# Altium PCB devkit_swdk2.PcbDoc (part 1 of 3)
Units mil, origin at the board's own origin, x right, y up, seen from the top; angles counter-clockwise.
Board outline 2700 x 2100 mil, 4 copper layers (Component Side, Internal Plane 1, Internal Layer 2, Bottom Layer), stack 57.8 mil thick; 223 components, 143 nets, 656 pads, 485 vias.
Unrouted connection lines stored in the file: 72.
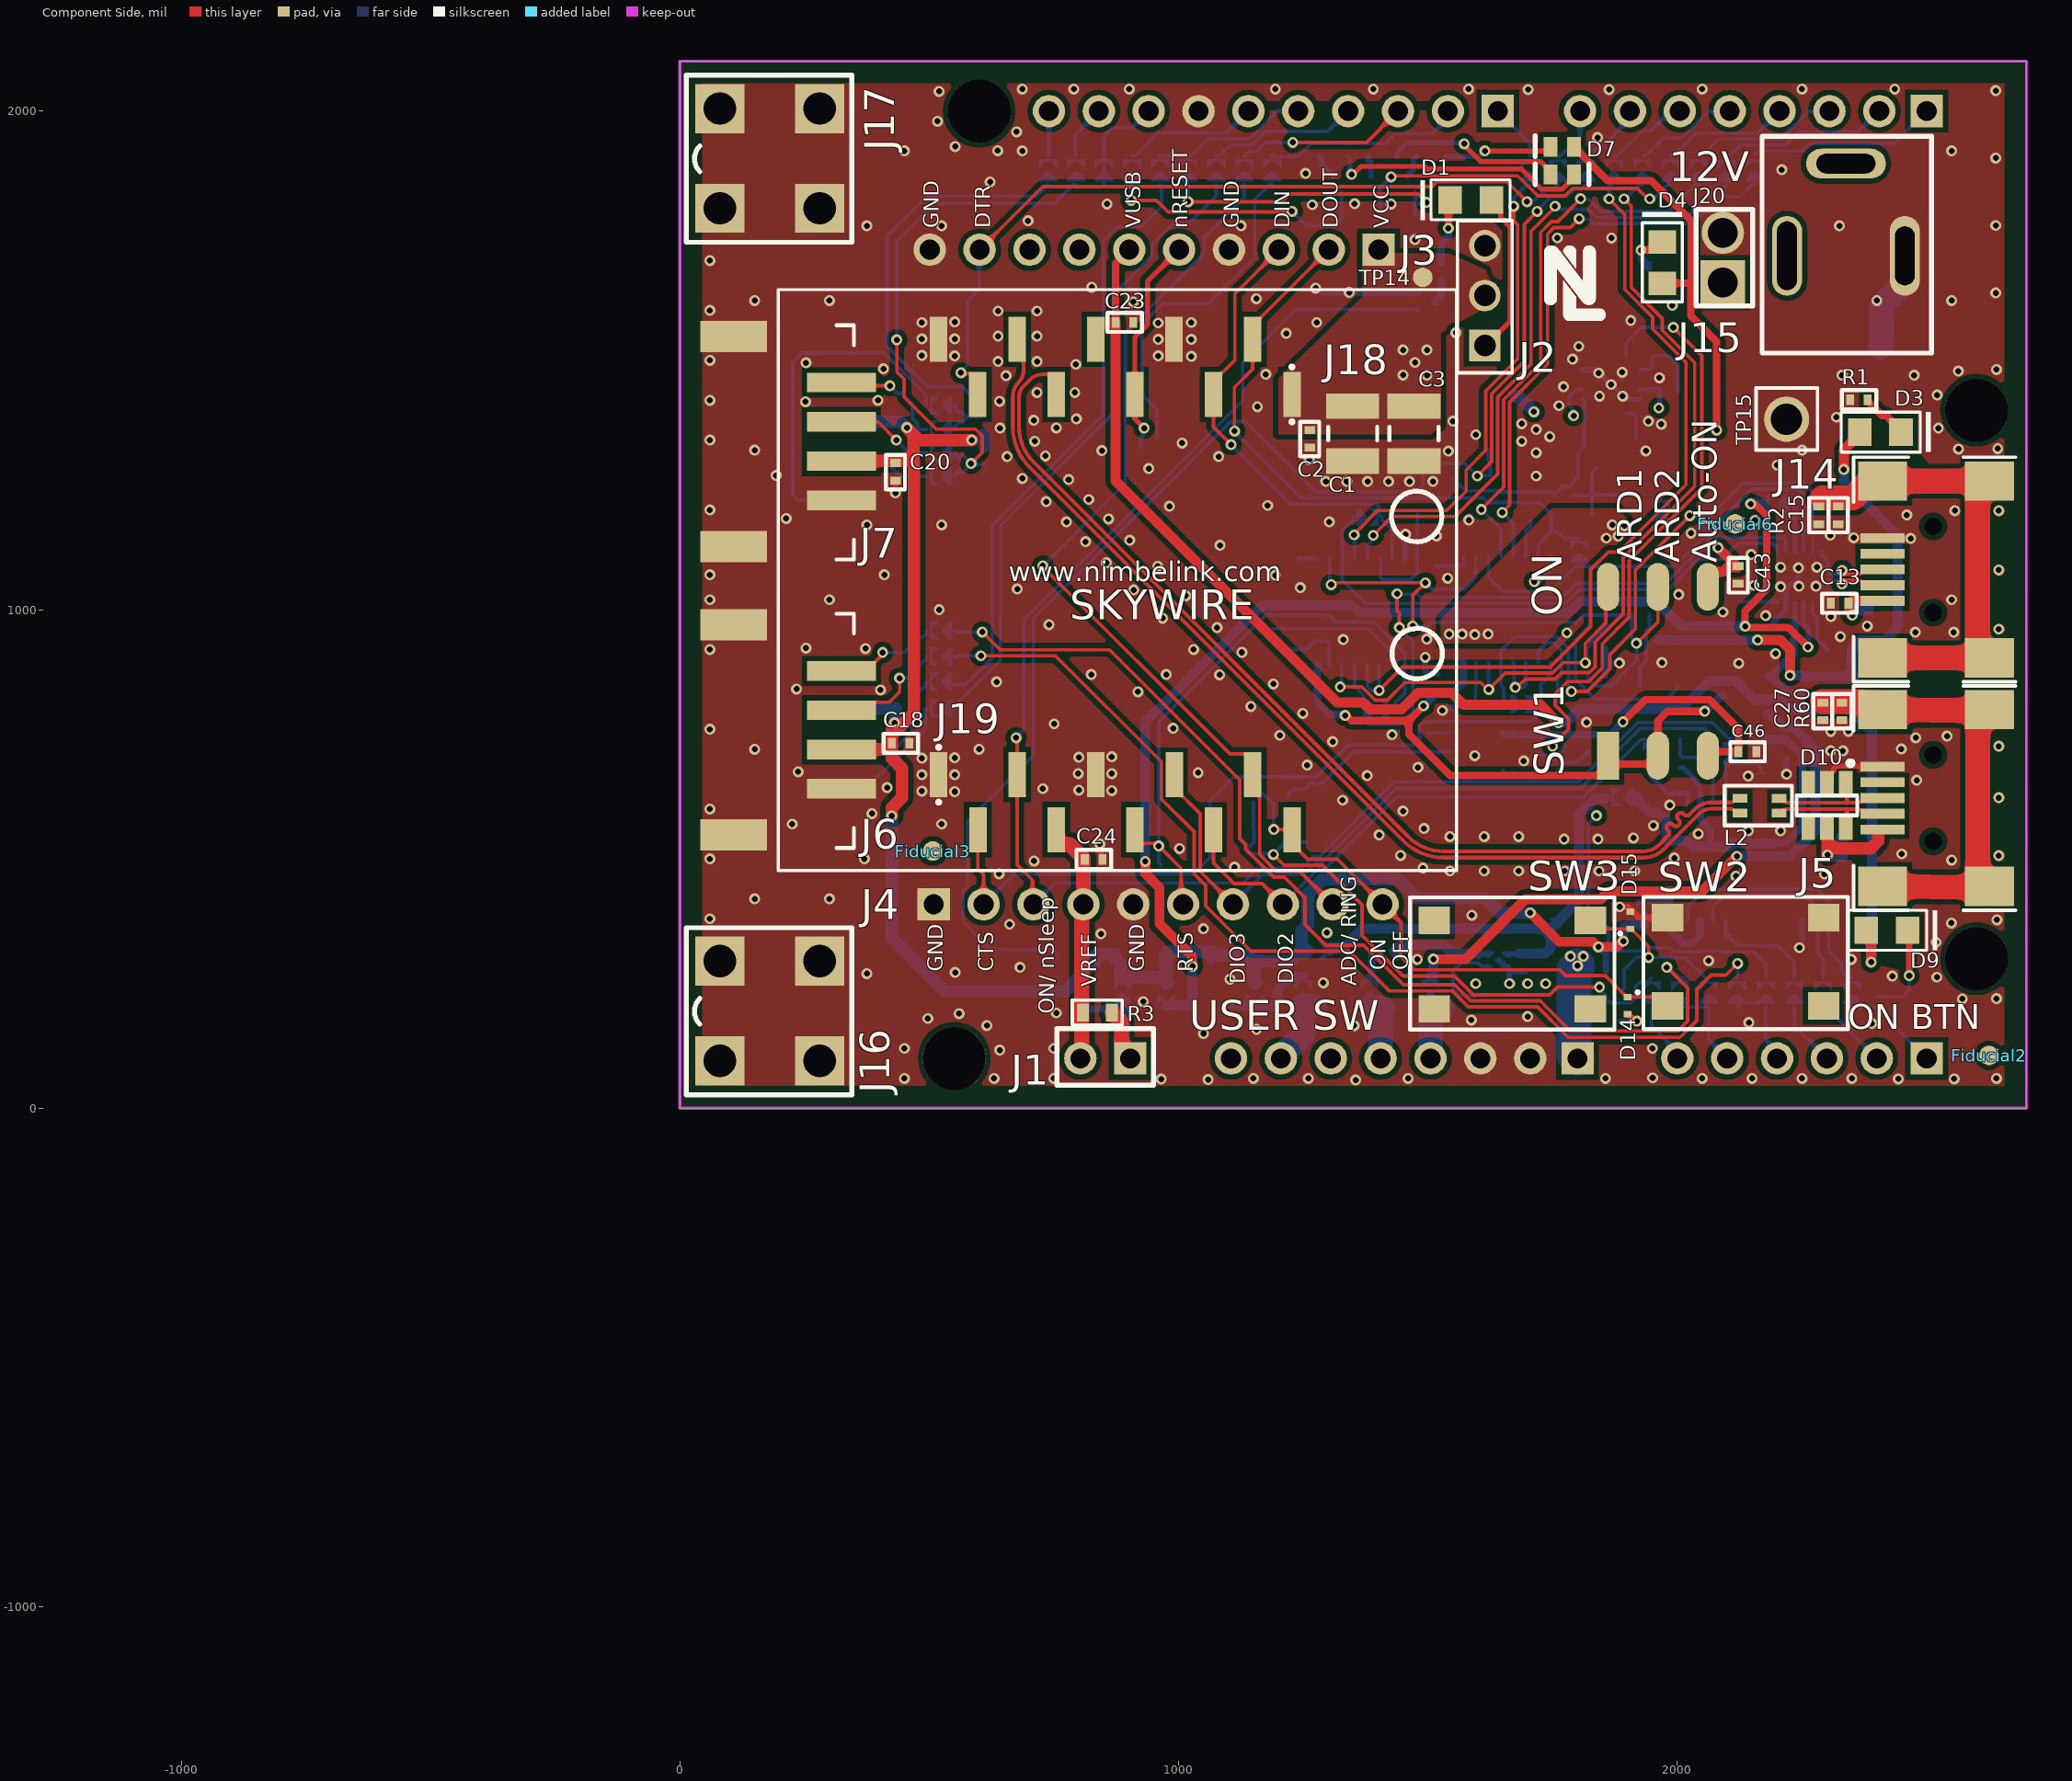
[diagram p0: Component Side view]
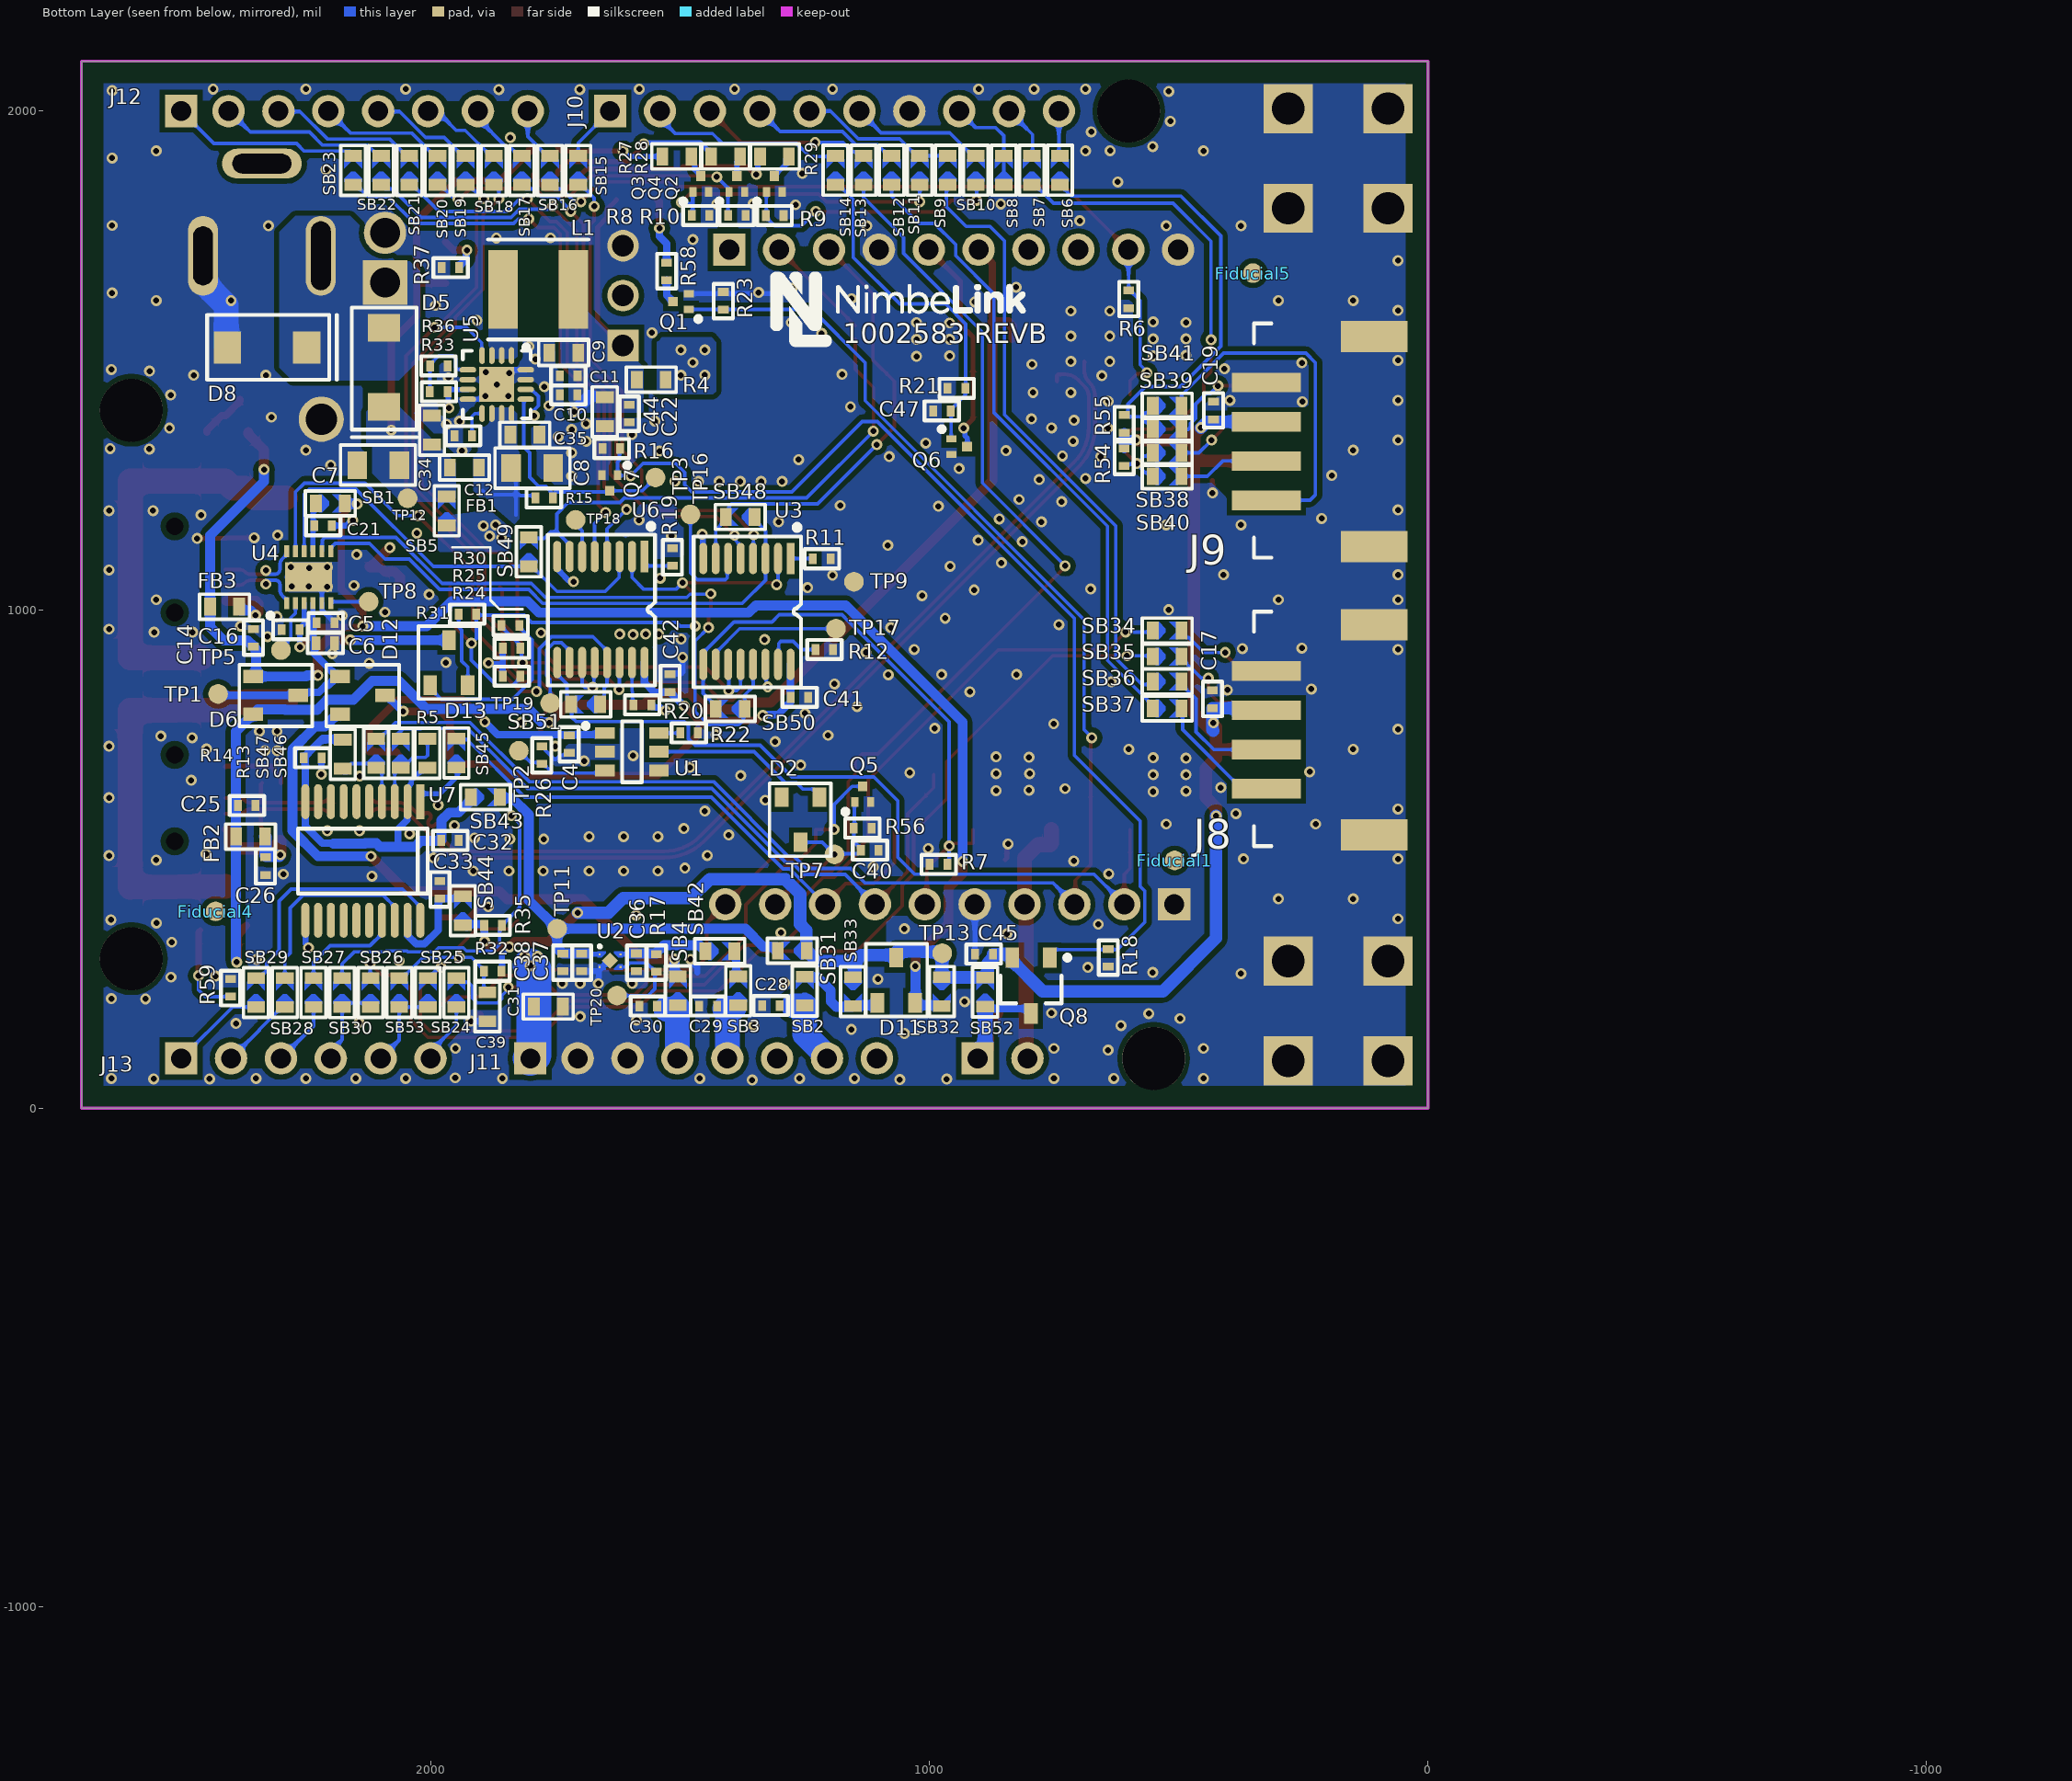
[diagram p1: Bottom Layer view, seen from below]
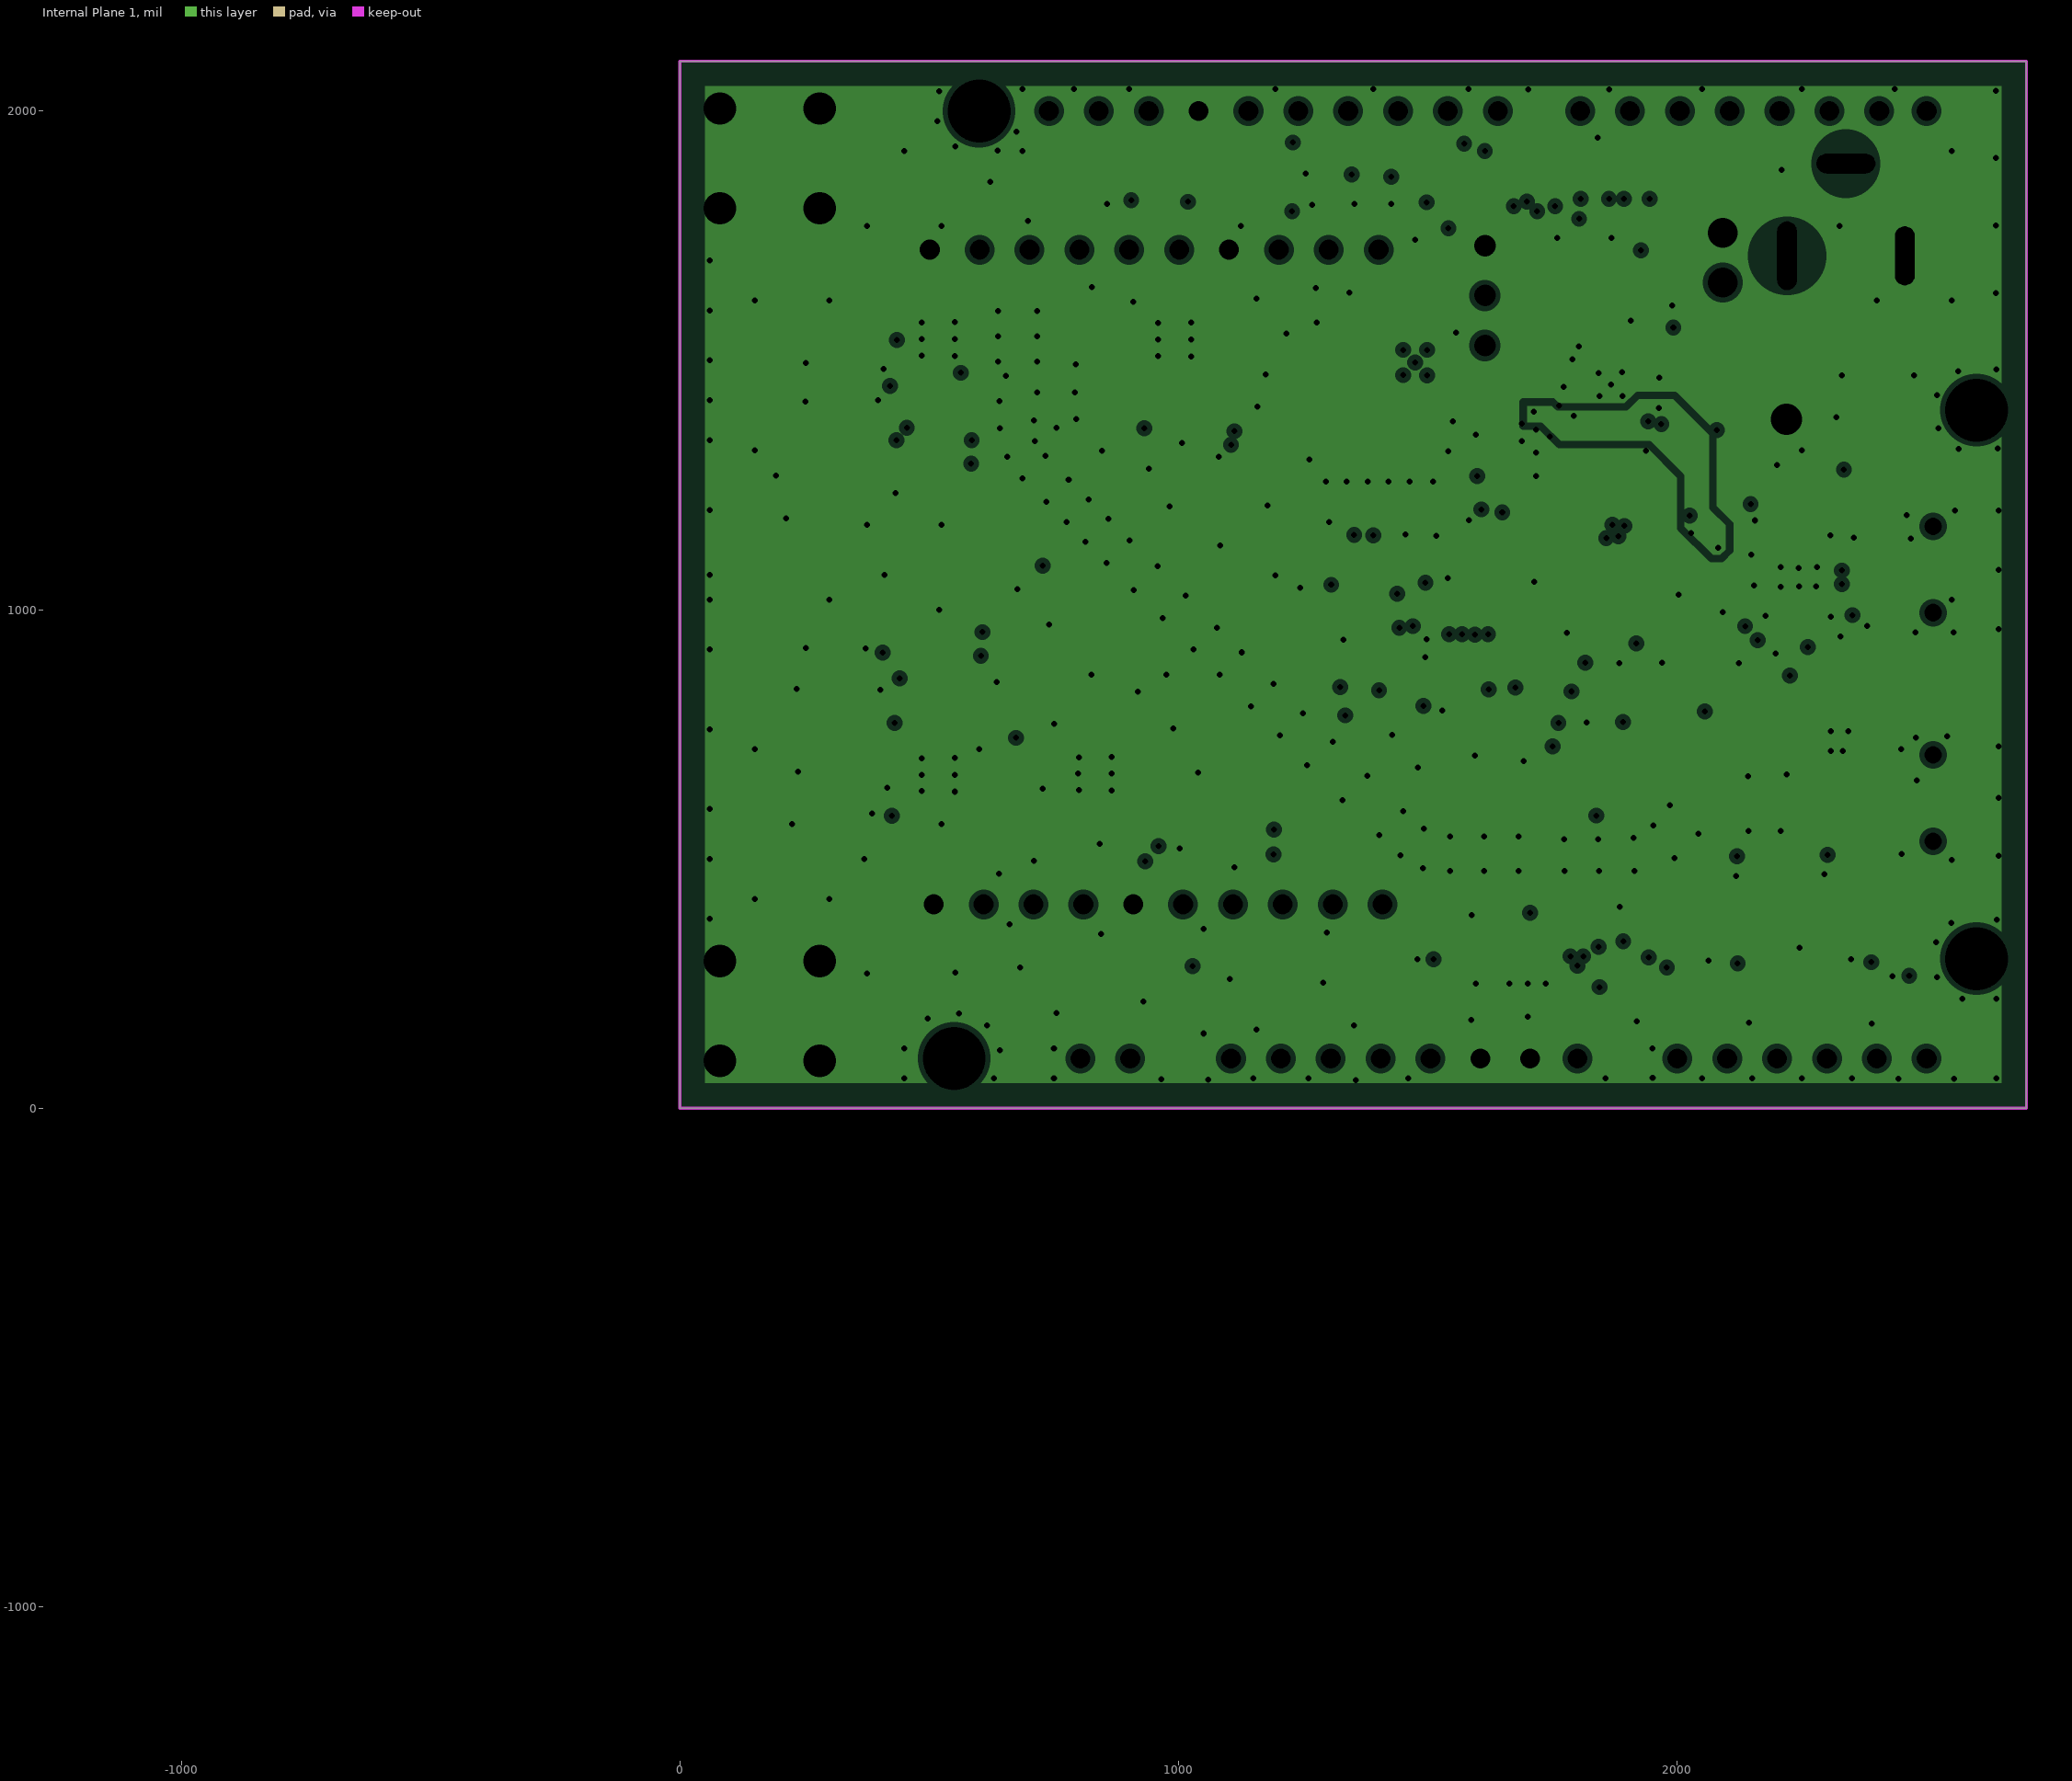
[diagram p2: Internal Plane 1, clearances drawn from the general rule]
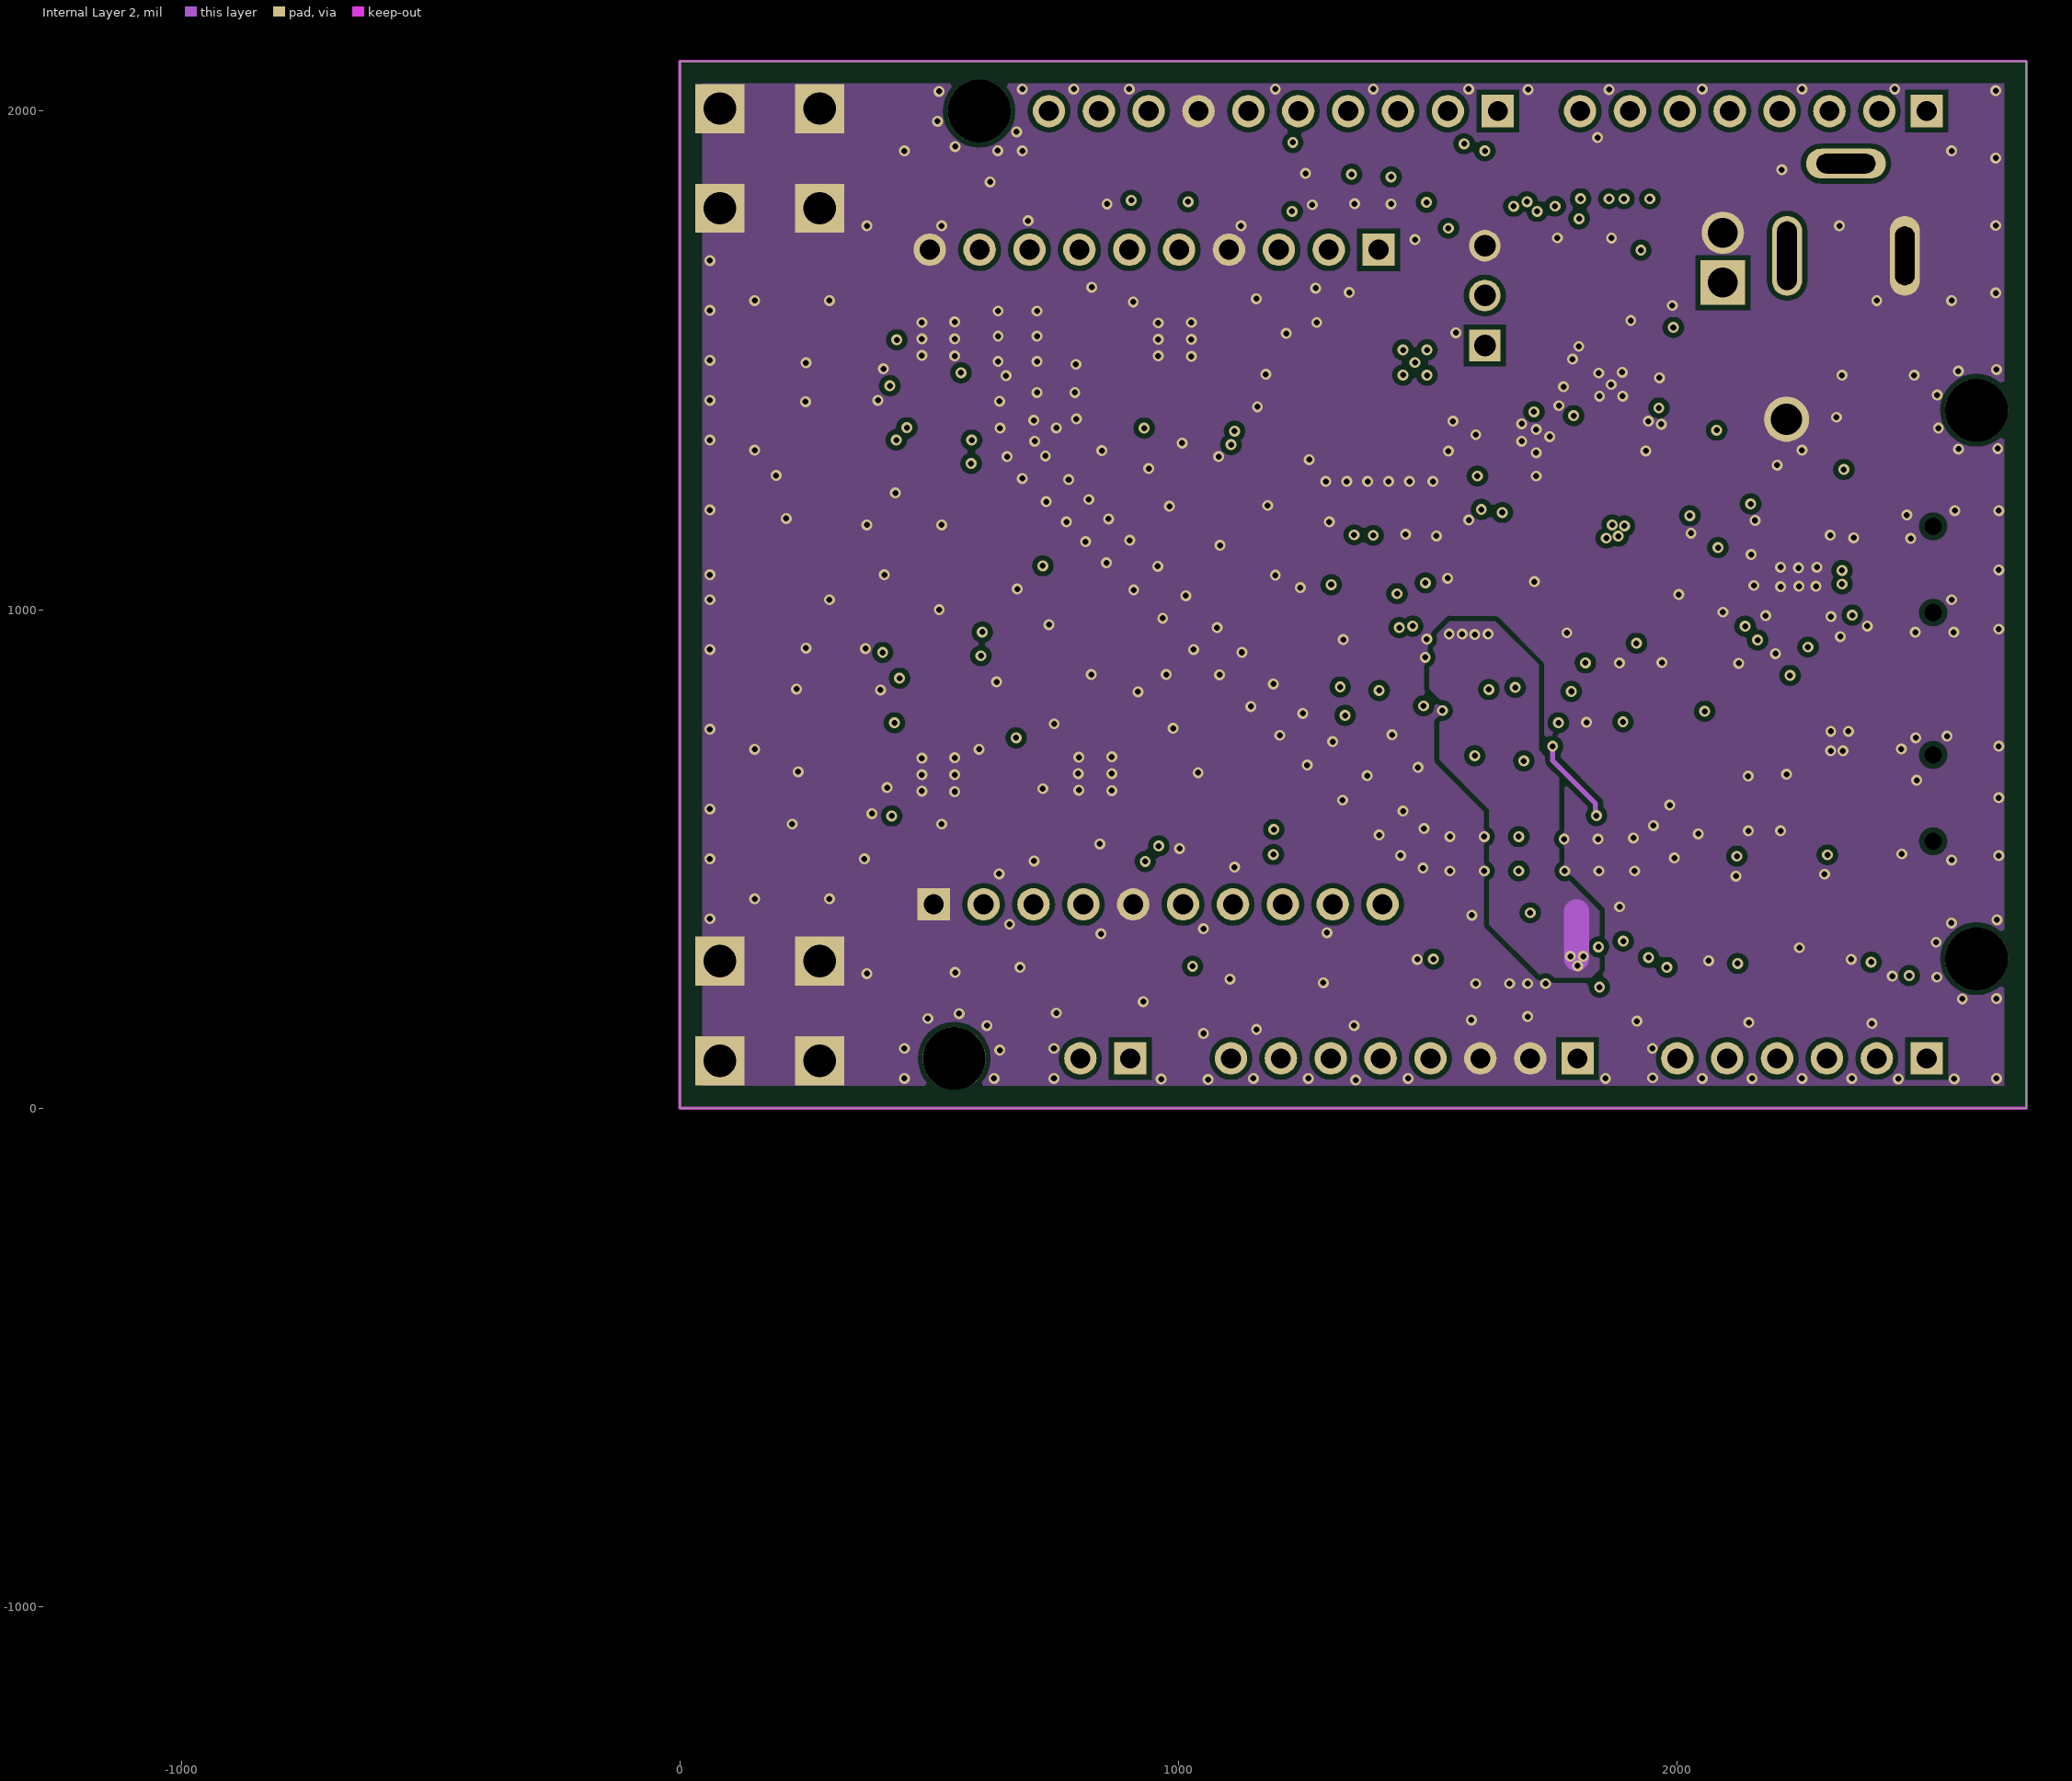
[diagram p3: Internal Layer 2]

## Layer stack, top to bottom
Top Solder: solder mask 1, Solder Resist, Dk 3.5
Component Side: signal copper 0.7
Dielectric 1: core 8.5, FR4-TG170, Dk 4.6
Internal Plane 1: plane copper 1.4, net (Multiple Nets)
Dielectric 3: prepreg 36.6, Dk 4.6
Internal Layer 2: signal copper 1.4
Dielectric 2: core 8.5, FR4-TG170, Dk 4.6
Bottom Layer: signal copper 0.7
Solder Side: solder mask 1, Solder Resist, Dk 3.5

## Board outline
0,0 0,2100 2700,2100 2700,0

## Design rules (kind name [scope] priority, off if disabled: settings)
Clearance Clearance_1 [InPolygon] p1: gap=10 ignorepadtopadclearanceinfootprint=FALSE except(0: Arc-Hole Track-Hole SMDPad-Hole THPad-Hole Via-Hole Fill-Hole Poly-Hole Region-Hole Text-Hole)
Clearance Clearance_2 [InNetClass('RF_T_LINE') vs InPolygon] p2: gap=20 ignorepadtopadclearanceinfootprint=FALSE except(0: Arc-Hole Track-Hole SMDPad-Hole THPad-Hole Via-Hole Fill-Hole Poly-Hole Region-Hole Text-Hole)
Clearance [All] p3: gap=5 ignorepadtopadclearanceinfootprint=FALSE
DiffPairsRouting [All] p1: maxlimit=50 minlimit=5 mostfreqgap=5 toplayer_minwidth=7 toplayer_maxwidth=10 toplayer_prefwidth=7.6 midlayer1_maxgap=10 midlayer1_minwidth=7 midlayer1_maxwidth=10 midlayer1_prefwidth=7.6 bottomlayer_minwidth=7 bottomlayer_maxwidth=10 bottomlayer_prefwidth=7.6 maxuncoupledlength=500
Height [All] p1: minheight=0 maxheight=10000 prefheight=500
HoleSize [All] p1: absolutevalues=TRUE maxlimit=500 minlimit=10 maxpercent=80.000 minpercent=20.000
MatchedLengths [InNetClass('DIFF90')] p1: tolerance=15 checknetsindiffpair=TRUE checkdiffpairvsdiffpair=FALSE checkxsignals=FALSE checkothers=FALSE
MinimumAnnularRing [All] p1: minimumring=5
MinimumSolderMaskSliver [All] p1: minsoldermaskwidth=0
PlaneClearance [All] p1: clearance=10
PlaneConnect PlaneConnect_1 [IsVia] p1: planeconnectstyle=Direct reliefexpansion=20 reliefentries=4 reliefconductorwidth=10 reliefairgap=10
PlaneConnect PlaneConnect_ThruHole [IsPad] p2: planeconnectstyle=Direct reliefexpansion=20 reliefentries=4 reliefconductorwidth=10 reliefairgap=10
PolygonConnect [All] p1: connectstyle=Direct reliefconductorwidth=10 reliefentries=4 polygonreliefangle="90 Angle" airgapwidth=10
RoutingVias [All] p1: holewidth=12 width=22 viastyle="Through Hole" minholewidth=10 minwidth=20 maxholewidth=100 maxwidth=150
SilkToSilkClearance [All] p1: silktosilkclearance=0
SilkToSolderMaskClearance [IsPad] p1: minsilkscreentomaskgap=0 clearancetoexposedcopper=TRUE
SolderMaskExpansion SolderMaskExpansion_1 [isVia] p1: expansion=-10
SolderMaskExpansion [All] p2: expansion=0
Width Width_RF_TRACE [InNetClass('RF_T_LINE')] p1: maxlimit=10 minlimit=8.54 preferedwidth=10 toplayer_maxwidth=8.54 toplayer_prefwidth=8.54 midlayer1_minwidth=10 bottomlayer_maxwidth=8.54 bottomlayer_prefwidth=8.54 minimp=50.000000 maximp=50.000000 favimp=50.000000
Width [All] p2: maxlimit=1000 minlimit=7 preferedwidth=10
22 further rules are at their usual default settings.

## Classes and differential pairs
component class Skywire: C1 C2 C3 C4 C22 C23 C24 C25 C26 C27 C40 C47 D1 D2 D9 D10 D14 FB2 J1 J2 J3 J4 J5 J16 J17 J18 J19 L2 Q1 Q5 Q6 R3 R4 R6 R7 R21 R22 R23 R26 R56 R58 R59 R60 SW2 TP2 TP7 TP14 U1
component class TOP: C5 C6 C13 C14 C15 C16 C21 C28 C29 C30 C31 C41 C42 C43 C46 D3 D6 D12 D13 FB3 Fiducial1 Fiducial2 Fiducial3 Fiducial4 Fiducial5 Fiducial6 J10 J11 J12 J13 J14 R1 R2 R11 R12 R19 R20 R24 R25 R30 R31 SB1 SB2 SB3 SB4 SB5 SB6 SB7 SB8 SB9 SB10 SB11 SB12 SB13 SB14 SB15 SB16 SB17 SB18 SB19 SB20 SB21 SB22 SB23 SB24 SB25 SB26 SB27 SB28 SB29 SB30 SB48 SB49 SB50 SB51 SB53 SW1 TP1 TP5 TP8 TP16 TP17 TP18 TP19 U3 U4 U6
component class Power: C7 C8 C9 C10 C11 C12 C34 C35 C36 C37 C38 C44 C45 D4 D5 D8 D11 FB1 J15 J20 L1 Q7 Q8 R15 R16 R17 R18 R33 R35 R36 R37 SB31 SB32 SB33 SB42 SB52 TP3 TP9 TP11 TP12 TP13 TP15 TP20 U2 U5
component class "Application Interfaces": C17 C18 C19 C20 C32 C33 C39 D7 D15 J6 J7 J8 J9 Q2 Q3 Q4 R5 R8 R9 R10 R13 R14 R27 R28 R29 R32 R54 R55 SB34 SB35 SB36 SB37 SB38 SB39 SB40 SB41 SB43 SB44 SB45 SB46 SB47 SW3 U7
differential pair CON_USB: +CON_USB_P -CON_USB_N
differential pair USB: +USB_P -USB_N
differential pair SKY_USB: +SKY_USB_P -SKY_USB_N

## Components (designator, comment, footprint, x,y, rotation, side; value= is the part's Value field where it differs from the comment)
C1 "1001241" CAPC3225X25N_1210 1349,1353.06 r270 top
C2 "" 0402 1263,1343 r270 top
C3 "1001241" CAPC3225X25N_1210 1472,1353.06 r270 top
C4 "" 0402 1722,731 r270 bottom
C5 "" 0402 2211,973.84 r180 bottom
C6 "C, 10 uF, 10V, X5R, 20%, 0402 CER" "0402 +-0.2mm Width" 2211,933 r180 bottom
C7 "C, 10 uF, 25V, 10% ,X5R, 0805 CER" 0805 2114,1290 r0 bottom
C8 "C, 10 uF, 25V, 10% ,X5R, 0805 CER" 0805 1787,1284 r180 bottom
C9 "1000932" 0603 1733,1515 r0 bottom
C10 "C, 0.1 uF, 16V, 10%, X7R, 0402 CER" 0402 1722.62,1431 r0 bottom
C11 "C, 0.1 uF, 16V, 10%, X7R, 0402 CER" 0402 1722.5,1469 r0 bottom
C12 "CAPACITOR" 0402 1934,1349 r0 bottom
C13 "" 0402 2326,1013 r180 top
C14 "" 0402 2355,943 r90 bottom
C15 "CAPACITOR" 0402 2322.58,1188.63 r90 top
C16 "" 0402 2280,960 r0 bottom
C17 "" 0402 432,820 r90 bottom
C18 "" 0402 442,732 r0 top
C19 "" 0402 430,1399 r90 bottom
C20 "" 0402 432,1277 r270 top
C21 "" 0402 2216.21,1168.29 r180 bottom
C22 "" 0402 1601.5,1394 r270 bottom
C23 "" 0402 891,1576 r0 top
C24 "" 0402 829,499 r0 top
C25 "" 0402 2369,607 r180 bottom
C26 "" 0402 2331,486 r270 bottom
C27 "CAPACITOR" 0402 2291.94,795.43 r90 top
C28 "" 0402 1317,206.13 r0 bottom
C29 "" 0402 1443,205.14 r0 bottom
C30 "" 0402 1563,205.14 r0 bottom
C31 "CAPACITOR" 0603 1764,204 r180 bottom
C32 "" 0402 1961.38,537 r180 bottom
C33 "" 0402 1981.1,437.82 r90 bottom
C34 "CAPACITOR" 0603 1997,1360 r90 bottom
C35 "CAPACITOR" 0603 1811,1351 r180 bottom
C36 "C, 1 uF, 10V, 10%, X5R, 0402 CER" 0402 1587.15,293.18 r270 bottom
C37 "C, 0.1 uF, 16V, 10%, X7R, 0402 CER" 0402 1697,293 r270 bottom
C38 "C, 1 uF, 10V, 10%, X5R, 0402 CER" 0402 1735,293 r270 bottom
C39 "CAPACITOR" 0603 1886,203.5 r270 bottom
C40 "" 0402 1120,517.5 r180 bottom
C41 "" 0402 1261,824 r180 bottom
C42 "" 0402 1519.69,852.06 r90 bottom
C43 "" 0402 2122,1070 r270 top
C44 "1000932" 0603 1650.5,1397 r270 bottom
C45 "C, 0.1 uF, 16V, 10%, X7R, 0402 CER" 0402 889.82,309.15 r0 bottom
C46 "" 0402 2140,715 r0 top
C47 "" 0402 974,1398.5 r0 bottom
D1 "LTST-C170GKT" D_LED_GREEN 1585.85,1822 r0 top
D2 "BAT54CLT1G" SOT23-STYLE9 1220.41,627.94 r0 bottom
D3 "LTST-C170GKT" D_LED_GREEN 2407,1356 r180 top
D4 "LTST-C170GKT" D_LED_GREEN 1969.89,1696 r270 top
D5 "B340A-13-F" "DO-214AC, SMA" 2093,1486 r270 bottom
D6 "BAT54CLT1G" SOT23-STYLE9 2359.94,866 r270 bottom
D7 "lTST-C19FD1WT" LTST-C19FD1WT 1745.76,1928 r90 top
D8 "SMAJ17A" "DO-214AC, SMA" 2328,1526 r180 bottom
D9 "LTST-C170GKT" D_LED_GREEN 2420.34,357 r180 top
D10 "USBLC6-4SC6" SOT23-6L 2300,607.27 r270 top
D11 "BAT54CLT1G" SOT23-STYLE9 1103.8,207.51 r180 bottom
D12 "BAT54CLT1G" SOT23-STYLE9 2185.49,866 r270 bottom
D13 "BAT54ALT1G" SOT23-STYLE9 2000.8,844.32 r180 bottom
D14 "TVS" SOD-923 1900,206 r270 top
D15 "TVS" SOD-923 1906,377 r90 top
FB1 "FERRITE" 0603 1932,1285 r180 bottom
FB2 "FERRITE" 0603 2360.82,545 r180 bottom
FB3 "FERRITE" 0603 2413,1006 r0 bottom
Fiducial1 "Fiducial 1mm" "Fiducial 1mm" 508,497 r90 bottom
Fiducial2 "Fiducial 1mm" "Fiducial 1mm" 2625,106 r90 top
Fiducial3 "Fiducial 1mm" "Fiducial 1mm" 507,516 r180 top
Fiducial4 "Fiducial 1mm" "Fiducial 1mm" 2431,395 r90 bottom
Fiducial5 "Fiducial 1mm" "Fiducial 1mm" 351,1675 r90 bottom
Fiducial6 "Fiducial 1mm" "Fiducial 1mm" 2115.94,1172 r180 top
J1 "PRPC002SFAN-RC" PRPC002SFAN-RC#1 903,100 r180 top
J2 "61300311121" 61300311121 1614,1530 r90 top
J3 "PRPC010SFAN-RC" PRPC010SFAN-RC 1401,1722 r180 top locked
J4 "PRPC010SFAN-RC" PRPC010SFAN-RC 509,409 r0 top
J5 "USB MINI B" 10033526-N3212LF 2743.32,622.17 r90 top
J6 "S4B-PH-SM4-TB(LF)(SN)" S4B-PH-SM4-TB(LF)(SN) 324,877 r90 top
J7 "S4B-PH-SM4-TB(LF)(SN)" S4B-PH-SM4-TB(LF)(SN) 324,1455.48 r90 top
J8 "S4B-PH-SM4-TB(LF)(SN)" S4B-PH-SM4-TB(LF)(SN) 324,640.78 r270 bottom
J9 "S4B-PH-SM4-TB(LF)(SN)" S4B-PH-SM4-TB(LF)(SN) 324,1219.26 r270 bottom
J10 "PRPC010SFAN-RC" PRPC010SFAN-RC 1640,2000 r180 bottom locked
J11 "PRPC008SFAN-RC" PRPC008SFAN-RC 1805,100 r180 bottom
J12 "PRPC008SFAN-RC" PRPC008SFAN-RC 2505,2000 r180 bottom
J13 "PRPC006SFAN-RC" PRPC006SFAN-RC 2500,100 r180 bottom
J14 "USB MINI B" 10033526-N3212LF 2743.32,1080.61 r90 top
J15 "PJ-202A" PJ-202A 2220,1709.68 r0 top
J16 "UFL to SMA" "UFL TO SMA" 80,295 r270 top locked
J17 "UFL to SMA" "UFL TO SMA" 80,2005 r270 top locked
J18 "1000865" NPPN101BFLC-RC 1227.31,1431.81 r270 top locked
J19 "1000865" NPPN101BFLC-RC 518.82,668.98 r90 top locked
J20 "PRPC002SFAN-RC" PRPC002SFAN-RC#2 2091.28,1656 r90 top
L1 "INDUCTOR" NRS5040 1784.13,1642 r180 bottom
L2 "SRF2012-900YA" SRF2012-900YA 2165,607 r0 top
Q1 "MOSFET_N" SOT-723 1498,1618 r0 bottom
Q2 "MOSFET_N" SOT-723 1310.39,1853.75 r90 bottom
Q3 "MOSFET_N" SOT-723 1458.25,1853.75 r90 bottom
Q4 "MOSFET_N" SOT-723 1385.75,1853.75 r90 bottom
Q5 "MOSFET_N" SOT-723 1133.25,629.75 r90 bottom
Q6 "MOSFET_N" SOT-723 940,1327 r180 bottom
Q7 "MOSFET_N" SOT-723 1640.75,1254.25 r270 bottom
Q8 "MOSFET_P" SOT95P300X115-3N 796,246 r270 bottom
R1 "R, 330, 1%, 1/10W, 0402" 0402 2363.59,1421.03 r0 top
R2 "R, 1M, 1%, 1/16W, 0402" 0402 2283.58,1188.63 r90 top
R3 "R, 0.1, 1%, 1/4W, 0603" 0603 837,192 r0 top
R4 "R, 0.1, 1%, 1/4W, 0603" 0603 1557.54,1461.37 r180 bottom
R5 "2K" 0603 2006.38,711.99 r270 bottom
R6 "R, 1K, 1%, 1/16W, 0402" 0402 600,1622 r90 bottom
R7 "R, 1K, 1%, 1/16W, 0402" 0402 982,489 r180 bottom
R8 "R, 100K, 1%, 1/16W,  0402" 0402 1458.25,1790.75 r0 bottom
R9 "R, 100K, 1%, 1/16W,  0402" 0402 1309.39,1790.59 r0 bottom
R10 "R, 100K, 1%, 1/16W,  0402" 0402 1385.39,1790.75 r0 bottom
R11 "R, 10K, 1%, 1/16W,  0402" 0402 1216,1102 r180 bottom
R12 "R, 10K, 1%, 1/16W,  0402" 0402 1211,919.87 r180 bottom
R13 "2K" 0603 2176,710 r90 bottom
R14 "R, 100K, 1%, 1/16W,  0402" 0402 2236,703 r0 bottom
R15 "R, 100K, 1%, 1/16W,  0402" 0402 1771.82,1224.15 r0 bottom
R16 "R, 100K, 1%, 1/16W,  0402" 0402 1637.76,1323 r180 bottom
R17 "R, 100K, 1%, 1/16W,  0402" 0402 1546.85,291.19 r90 bottom
R18 "R, 1M, 1%, 1/16W, 0402" 0402 641,301 r90 bottom
R19 "R, 10K, 1%, 1/16W,  0402" 0402 1515,1106 r270 bottom
R20 "R, 10K, 1%, 1/16W,  0402" 0402 1574.8,809 r0 bottom
R21 "R, 10K, 1%, 1/16W,  0402" 0402 946,1444 r180 bottom
R22 "R, 10K, 1%, 1/16W,  0402" 0402 1481,753 r0 bottom
R23 "R, 1M, 1%, 1/16W, 0402" 0402 1413,1620 r270 bottom
R24 "R, 100K, 1%, 1/16W,  0402" 0402 1838.18,866.46 r180 bottom
R25 "R, 100K, 1%, 1/16W,  0402" 0402 1838.18,922.36 r180 bottom
R26 "R, 10K, 1%, 1/16W,  0402" 0402 1777,708.78 r270 bottom
R27 "2K" 0603 1506.19,1908.94 r0 bottom
R28 "2K" 0603 1408.29,1908.94 r0 bottom
R29 "2K" 0603 1310.39,1908.94 r0 bottom
R30 "RESISTOR" 0402 1840.24,968.15 r180 bottom
R31 "RESISTOR" 0402 1925.5,991 r0 bottom
R32 "R, 10K, 1%, 1/16W,  0402" 0402 1875,275 r0 bottom
R33 "Resistor, 715K, 1%, 1/10W, 0402" 0402 1984.18,1437 r180 bottom
R35 "R, 100K, 1%, 1/16W,  0402" 0402 1874.27,367 r0 bottom
R36 "Resistor, 178K, 1%, 1/10W, 0402" 0402 1983,1489 r0 bottom
R37 "R, 1K, 1%, 1/16W, 0402" 0402 1960.55,1686 r180 bottom
R54 "R, 2.2K, 1%, 1/10W, 0402" 0402 609,1305.5 r90 bottom
R55 "R, 2.2K, 1%, 1/10W, 0402" 0402 609.03,1372.94 r270 bottom
R56 "R, 10K, 1%, 1/16W,  0402" 0402 1133.01,561.9 r0 bottom
R58 "R, 330, 1%, 1/10W, 0402" 0402 1526.46,1678 r90 bottom
R59 "R, 330, 1%, 1/10W, 0402" 0402 2401,242 r270 bottom
R60 "R, 1M, 1%, 1/16W, 0402" 0402 2329.89,795.43 r90 top
SB1 "Solder Bridge" "SOLDER BRIDGE 0603 CLOSED" 2201,1213 r0 bottom
SB2 "Solder Bridge" "SOLDER BRIDGE 0603 CLOSED" 1249.63,235 r270 bottom
SB3 "Solder Bridge" "SOLDER BRIDGE 0603 CLOSED" 1383.03,235.57 r270 bottom
SB4 "Solder Bridge" "SOLDER BRIDGE 0603 CLOSED" 1504,235.57 r270 bottom
SB5 "Solder Bridge" "SOLDER BRIDGE 0603 CLOSED" 1967.5,1198 r270 bottom
SB6 "Solder Bridge" "SOLDER BRIDGE 0603 CLOSED" 738,1881.19 r270 bottom
SB7 "Solder Bridge" "SOLDER BRIDGE 0603 CLOSED" 794.25,1881.19 r270 bottom
SB8 "Solder Bridge" "SOLDER BRIDGE 0603 CLOSED" 850.5,1881.19 r270 bottom
SB9 "Solder Bridge" "SOLDER BRIDGE 0603 CLOSED" 963,1881.19 r270 bottom
SB10 "Solder Bridge" "SOLDER BRIDGE 0603 CLOSED" 906.75,1881.19 r270 bottom
SB11 "Solder Bridge" "SOLDER BRIDGE 0603 CLOSED" 1019.25,1881.19 r270 bottom
SB12 "Solder Bridge" "SOLDER BRIDGE 0603 CLOSED" 1075.5,1881.19 r270 bottom
SB13 "Solder Bridge" "SOLDER BRIDGE 0603 CLOSED" 1131.75,1881.19 r270 bottom
SB14 "Solder Bridge" "SOLDER BRIDGE 0603 CLOSED" 1188,1881.19 r270 bottom
SB15 "Solder Bridge" "SOLDER BRIDGE 0603 CLOSED" 1704,1881.01 r270 bottom
SB16 "Solder Bridge" "SOLDER BRIDGE 0603 CLOSED" 1760.41,1881.01 r270 bottom
SB17 "Solder Bridge" "SOLDER BRIDGE 0603 CLOSED" 1816.82,1881.01 r270 bottom
SB18 "Solder Bridge" "SOLDER BRIDGE 0603 CLOSED" 1873.23,1881.01 r270 bottom
SB19 "Solder Bridge" "SOLDER BRIDGE 0603 CLOSED" 1929.64,1881.01 r270 bottom
SB20 "Solder Bridge" "SOLDER BRIDGE 0603 CLOSED" 1986.05,1881.01 r270 bottom
SB21 "Solder Bridge" "SOLDER BRIDGE 0603 CLOSED" 2042.46,1881.01 r270 bottom
SB22 "Solder Bridge" "SOLDER BRIDGE 0603 CLOSED" 2098.87,1881.01 r270 bottom
SB23 "Solder Bridge" "SOLDER BRIDGE 0603 CLOSED" 2155.28,1881.01 r270 bottom
SB24 "Solder Bridge" "SOLDER BRIDGE 0603 CLOSED" 1948.25,232 r270 bottom
SB25 "Solder Bridge" "SOLDER BRIDGE 0603 CLOSED" 2005.5,232 r270 bottom
SB26 "Solder Bridge" "SOLDER BRIDGE 0603 CLOSED" 2120,232 r270 bottom
SB27 "Solder Bridge" "SOLDER BRIDGE 0603 CLOSED" 2234.75,232 r270 bottom
SB28 "Solder Bridge" "SOLDER BRIDGE 0603 CLOSED" 2292.25,232 r270 bottom
SB29 "Solder Bridge" "SOLDER BRIDGE 0603 CLOSED" 2350,232 r270 bottom
SB30 "Solder Bridge" "SOLDER BRIDGE 0603 CLOSED" 2177.37,232 r270 bottom
SB31 "Solder Bridge" "SOLDER BRIDGE 0603" 1274.63,316 r180 bottom
SB32 "Solder Bridge" "SOLDER BRIDGE 0603" 975,234 r90 bottom
SB33 "Solder Bridge" "SOLDER BRIDGE 0603" 1153,233.88 r90 bottom
SB34 "Solder Bridge" "SOLDER BRIDGE 0603 CLOSED" 523.03,958 r0 bottom
SB35 "Solder Bridge" "SOLDER BRIDGE 0603 CLOSED" 523.03,906 r0 bottom
SB36 "Solder Bridge" "SOLDER BRIDGE 0603 CLOSED" 523.03,856 r0 bottom
SB37 "Solder Bridge" "SOLDER BRIDGE 0603 CLOSED" 523.03,802 r0 bottom
SB38 "Solder Bridge" "SOLDER BRIDGE 0603 CLOSED" 523.03,1314.72 r0 bottom
SB39 "Solder Bridge" "SOLDER BRIDGE 0603 CLOSED" 523.03,1361.83 r0 bottom
SB40 "Solder Bridge" "SOLDER BRIDGE 0603 CLOSED" 523.03,1267.61 r0 bottom
SB41 "Solder Bridge" "SOLDER BRIDGE 0603 CLOSED" 523.03,1408.94 r0 bottom
SB42 "Solder Bridge" "SOLDER BRIDGE 0603 CLOSED" 1420,315 r0 bottom
SB43 "Solder Bridge" "SOLDER BRIDGE 0603 CLOSED" 1890,624 r0 bottom
SB44 "Solder Bridge" "SOLDER BRIDGE 0603 CLOSED" 1935.3,396.13 r270 bottom
SB45 "Solder Bridge" "SOLDER BRIDGE 0603 CLOSED" 1948.25,712.52 r270 bottom
SB46 "Solder Bridge" "SOLDER BRIDGE 0603 CLOSED" 2059.58,712 r270 bottom
SB47 "Solder Bridge" "SOLDER BRIDGE 0603 CLOSED" 2109,712 r270 bottom
SB48 "Solder Bridge" "SOLDER BRIDGE 0603" 1379,1186 r180 bottom
SB49 "Solder Bridge" "SOLDER BRIDGE 0603" 1802.82,1116 r270 bottom
SB50 "Solder Bridge" "SOLDER BRIDGE 0603" 1399.15,801 r180 bottom
SB51 "Solder Bridge" "SOLDER BRIDGE 0603" 1689,810 r180 bottom
SB52 "Solder Bridge" "SOLDER BRIDGE 0603" 888,233 r270 bottom
SB53 "Solder Bridge" "SOLDER BRIDGE 0603 CLOSED" 2062.75,232 r270 bottom
SW1 "DIP-3pin" 219-3MSTR 1961,876.54 r90 top
SW2 "PTS645SM43SMTR92 LFS" "PTS645SM43SMTR92 LFS" 2137,294 r180 top locked
SW3 "PTS645SM43SMTR92 LFS" "PTS645SM43SMTR92 LFS" 1669,288 r0 top locked
TP1 "Test Point 1mm" "Test_Point 1mm" 2426,831 r180 bottom
TP2 "Test Point 1mm" "Test_Point 1mm" 1823,717 r90 bottom
TP3 "Test Point 1mm" "Test_Point 1mm" 1549,1265 r0 bottom
TP5 "Test Point 1mm" "Test_Point 1mm" 2300,919 r90 bottom
TP7 "Test Point 1mm" "Test_Point 1mm" 1190,509 r90 bottom
TP8 "Test Point 1mm" "Test_Point 1mm" 2124,1016 r90 bottom
TP9 "Test Point 1mm" "Test_Point 1mm" 1151,1056 r90 bottom
TP11 "Test Point 1mm" "Test_Point 1mm" 1746,360 r90 bottom
TP12 "Test Point 1mm" "Test_Point 1mm" 2046,1223.5 r90 bottom
TP13 "Test Point 1mm" "Test_Point 1mm" 974,311 r90 bottom
TP14 "Test Point 1mm" "Test_Point 1mm" 1489.5,1666.5 r90 top
TP15 "Test Point TH" Keystone_5011 2218.99,1382.15 r90 top
TP16 "Test Point 1mm" "Test_Point 1mm" 1479,1191 r90 bottom
TP17 "Test Point 1mm" "Test_Point 1mm" 1187,961.87 r90 bottom
TP18 "Test Point 1mm" "Test_Point 1mm" 1709,1180.09 r90 bottom
TP19 "Test Point 1mm" "Test_Point 1mm" 1760,812.5 r90 bottom
TP20 "Test Point 1mm" "Test_Point 1mm" 1626,226 r90 bottom
U1 "TPL5111" SOT95P280X110-6N 1596.28,715 r180 bottom
U2 "NCP114AMX180TCG" NCP114AMX180TCG 1640,296 r270 bottom
U3 "SN74CBT3253CDBQR" SN74CBT3253CDBQR 1278.25,1102.68 r270 bottom
U4 "FT234XD" QFN45P300X300X80_HS-13N 2244.43,1065 r90 bottom
U5 "1001037" QFN50P300X300X100_HS-17N 1867.19,1451.53 r270 bottom
U6 "SN74CBT3253CDBQR" SN74CBT3253CDBQR 1571,1106.52 r270 bottom
U7 "TXS0108EPWR" "TSSOP-20 6.5x6.4mm" 2020.41,615.1 r270 bottom

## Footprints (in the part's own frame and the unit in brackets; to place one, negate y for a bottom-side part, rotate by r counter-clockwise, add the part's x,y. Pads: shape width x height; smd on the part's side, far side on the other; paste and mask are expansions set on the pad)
219-3MSTR [mm]
  rect 2.44x1.13 smd: 1(-4.3,2.54)
  oval 2.44x1.13 smd: 2(-4.3,0) 3(-4.3,-2.54) 4(4.3,-2.54) 5(4.3,0) 6(4.3,2.54)
  body extent -4.95,-4.55 4.96,4.54, height 4.28
0402 [mm]
  rect 0.4x0.55 smd: 1(-0.438,0.004) 2(0.462,0.004)
  silkscreen extent -0.85,-0.49 0.9,0.49, body extent -0.5,-0.25 0.5,0.25, height 0.3
"0402 +-0.2mm Width" [mm]
  rect 0.45x0.7 smd: 1(-0.475,0) 2(0.475,0)
  silkscreen extent -0.9,-0.53 0.9,0.53, body extent -0.6,-0.35 0.6,0.35, height 0.71
0603 [mm]
  rect 0.6x0.9 smd: 1(-0.737,0) 2(0.737,0)
  silkscreen extent -1.27,-0.64 1.27,0.64, body extent -0.8,-0.38 0.8,0.42, height 0.45
0805 [mm]
  rect 1x1.4 smd: 1(-1.3,0) 2(0.838,0)
  silkscreen extent -2.12,-1.03 1.69,1.02, body extent -1.21,-0.6 0.79,0.65, height 0.5
10033526-N3212LF [mm]
  rect 0x0 hole 0.9 unplated: 0(-2.2,5.85) 0(2.2,5.85)
  rect 0.5x2.25 smd: 1(-1.6,8.43) 2(-0.8,8.43) 3(0,8.43) 4(0.8,8.43) 5(1.6,8.43)
  rect 2x2.5 smd: 6(-4.5,8.43) 6(-4.5,2.98) 6(4.5,8.43) 6(4.5,2.98)
  silkscreen extent -5.71,1.65 5.72,9.91, body extent -4.95,0 4.95,9.4, height 4.05
61300311121 [mm]
  rect 1.61x1.61 hole 1.1: 1(0,0)
  round 1.61 hole 1.1: 2(2.54,0) 3(5.08,0)
  silkscreen extent -1.4,-1.4 6.35,1.4
CAPC3225X25N_1210 [mm] "Chip Capacitor, 2-Leads, 1210"
  rect 1.3x2.7 smd: 1(-1.4,0) 2(1.4,0)
  silkscreen extent -0.35,-1.25 0.35,1.25, body extent -1.7,-1.35 1.7,1.35, height 2.5
D_LED_GREEN [mm]
  rect 1.2x1.4 smd: 1(1.05,0) 2(-1.05,0)
  silkscreen extent -2.57,-1.03 2,1.02, body extent -1.07,-0.64 1.13,0.64, height 1.1
"DO-214AC, SMA" [mm]
  rect 1.4x1.64 smd: A(-2.015,0) K(2.015,0)
  silkscreen extent -3.05,-1.65 3.56,1.65, body extent -2.35,-1.46 2.35,1.46, height 2.5
"Fiducial 1mm" [mm]
  round 1 smd paste-0.5: Fiducial(0,0)
Keystone_5011 [mm]
  round 2.3 hole 1.6: 1(-0.004,0)
  silkscreen extent -1.58,-1.57 1.58,1.55, body extent -1.59,-1.59 1.58,1.59, height 8.13
LTST-C19FD1WT [mm]
  rect 1x0.7 smd: 1(0,0) 2(-1.4,0) 3(-1.4,-1.2) 4(0,-1.2)
  silkscreen extent -1.93,-1.95 0.56,0.77, body extent -1.79,-1.42 0.37,0.23, height 0.55
NCP114AMX180TCG [mm]
  rect 0.1x0.1 smd: 1(-0.325,-0.535) 2(0.325,-0.535) 3(0.325,0.535) 4(-0.325,0.535)
  rect 0.58x0.58 smd rot 45: 5(0,0)
  Component Side region: -0.475,0.21 -0.475,0.65 -0.175,0.65 -0.175,0.42 -0.385,0.21
  Component Side region: 0.475,0.21 0.475,0.65 0.175,0.65 0.175,0.42 0.385,0.21
  Component Side region: 0.475,-0.21 0.475,-0.65 0.175,-0.65 0.175,-0.42 0.385,-0.21
  Component Side region: -0.475,-0.21 -0.475,-0.65 -0.175,-0.65 -0.175,-0.42 -0.385,-0.21
  silkscreen extent -0.75,-0.55 -0.7,-0.5, body extent -0.5,-0.5 0.5,0.5, height 0.4
NPPN101BFLC-RC [mm] "Skywire Footprint with surfacemount pads"
  rect 2.29x0.89 smd: 1(0,0) 2(-2.8,-2) 3(0,-4) 4(-2.8,-6) 5(0,-8) 6(-2.8,-10) 7(0,-12) 8(-2.8,-14) 9(0,-16) 10(-2.8,-18)
  silkscreen extent -1.43,-0.03 1.43,0.03, body extent -3.54,-19.24 0.91,1.26, height 4.5
NRS5040 [mm]
  rect 1.5x4 smd: 1(-1.8,0) 2(1.8,0)
  silkscreen extent -2.55,-2.55 2.55,2.55, body extent -2.55,-2.55 2.55,2.55, height 4.1
PJ-202A [mil] "PJ-202A  Barrel Plug"
  oval 60x160 hole 39.37 slot 137.8 at 90 deg: 1(0,0)
  oval 160x60 hole 39.37 slot 118.11 at 0 deg: 2(118.11,185.04)
  oval 60x160 hole 39.37 slot 118.11 at 90 deg: 3(236.22,0)
  silkscreen extent -50,-195 290,240, body extent -28,-180 538,190, height 433
PRPC002SFAN-RC#1 [mil]
  rect 65x65 hole 40: 1(0,0)
  round 65 hole 40: 2(100,0)
  silkscreen extent -47,-60 147,54
PRPC002SFAN-RC#2 [mil]
  rect 90x90 hole 60: 1(0,0)
  round 85 hole 60: 2(100,0)
  silkscreen extent -47,-60 147,54
PRPC006SFAN-RC [mil]
  rect 65x65 hole 40: 1(0,0)
  round 65 hole 40: 2(100,0) 3(200,0) 4(300,0) 5(400,0) 6(500,0)
  body extent -50,-50 550,50, height 417
PRPC008SFAN-RC [mil]
  rect 65x65 hole 40: 1(5,0)
  round 65 hole 40: 2(100,0) 3(200,0) 4(300,0) 5(400,0) 6(500,0) 7(600,0) 8(700,0)
  body extent -45,-50 755,50, height 417
PRPC010SFAN-RC [mil]
  rect 65x65 hole 40: 1(0,0)
  round 65 hole 40: 2(100,0) 3(200,0) 4(300,0) 5(400,0) 6(500,0) 7(600,0) 8(700,0) 9(800,0) 10(900,0)
"PTS645SM43SMTR92 LFS" [mm]
  rect 1.6x1.4 smd: 1(-3.975,2.25) 2(3.975,2.25) 3(-3.975,-2.25) 4(3.975,-2.25)
  silkscreen extent -5.21,-3.3 5.21,3.43, body extent -4.2,-3.05 4.32,2.92, height 4.3
QFN45P300X300X80_HS-13N [mm] "QFN, 12-Leads, Body 3.00x3.00mm, Pitch 0.45mm, Thermal Pad 1.58x2.48mm, IPC Medium Density"
  rect 0.6x0.25 smd: 1(-1.325,1.125) 2(-1.325,0.675) 3(-1.325,0.225) 4(-1.325,-0.225) 5(-1.325,-0.675) 6(-1.325,-1.125) 7(1.325,-1.125) 8(1.325,-0.675) 9(1.325,-0.225) 10(1.325,0.225) 11(1.325,0.675) 12(1.325,1.125)
  rect 1.5x2.4 smd: 13(0.013,0)
  silkscreen extent -2.07,1.83 -1.83,2.08, body extent -1.5,-1.5 1.5,1.5, height 0.8
QFN50P300X300X100_HS-17N [mm] "QFN, 16-Leads, Body 3.00x3.00mm, Pitch 0.50mm, Thermal Pad 1.78x1.78mm, IPC Medium Density"
  oval 0.85x0.28 smd: 1(-1.475,0.75) 2(-1.475,0.25) 3(-1.475,-0.25) 4(-1.475,-0.75) 9(1.475,-0.75) 10(1.475,-0.25) 11(1.475,0.25) 12(1.475,0.75)
  oval 0.28x0.85 smd: 5(-0.75,-1.475) 6(-0.25,-1.475) 7(0.25,-1.475) 8(0.75,-1.475) 13(0.75,1.475) 14(0.25,1.475) 15(-0.25,1.475) 16(-0.75,1.475)
  rect 1.78x1.78 smd paste-0.8: 17(0,0)
  silkscreen extent -2.02,-1.72 1.73,1.72, body extent -1.58,-1.57 1.57,1.58, height 1
S4B-PH-SM4-TB(LF)(SN) [mm]
  rect 1x3.5 smd: 1(-6,0) 2(-4,0) 3(-2,0) 4(0,0)
  rect 1.6x3.4 smd: 5(-8.35,5.5) 5(2.35,5.5)
  silkscreen extent -9.02,-0.64 2.92,0.25
SN74CBT3253CDBQR [mm]
  rect 1.6x0.4 smd: 1(0,0)
  oval 1.6x0.4 smd: 2(0,-0.635) 3(0,-1.27) 4(0,-1.905) 5(0,-2.54) 6(0,-3.175) 7(0,-3.81) 8(0,-4.445) 9(5.4,-4.445) 10(5.4,-3.81) 11(5.4,-3.175) 12(5.4,-2.54) 13(5.4,-1.905) 14(5.4,-1.27) 15(5.4,-0.635) 16(5.4,0)
  silkscreen extent -1.71,-4.93 6.57,0.53, body extent -0.44,-4.7 5.78,0.38, height 1.8
SOD-923 [mm] "SODFL, 2-Leads, Body 0.60x1.00mm, IPC Medium Density"
  rect 0.325x0.4 smd: A(0.437,0) K(-0.437,0)
  silkscreen extent -0.72,0.48 -0.63,0.58, body extent -0.53,-0.33 0.53,0.33, height 0.45
"SOLDER BRIDGE 0603" [mm]
  rect 0.6x0.9 smd: 1(-0.737,0) 2(0.737,0)
  Component Side region: 0.075,0.1 0.075,-0.1 0.425,-0.45 0.575,-0.45 0.575,0.45 0.425,0.45
  Component Side region: -0.452,0.1 -0.102,0.45 -0.552,0.45 -0.552,-0.45 -0.102,-0.45 -0.452,-0.1
  silkscreen extent -1.27,-0.64 1.27,0.64, body extent -0.8,-0.38 0.8,0.42, height 0.45
"SOLDER BRIDGE 0603 CLOSED" [mm]
  rect 0.6x0.9 smd paste+0: 1(-0.737,0)
  rect 0.6x0.9 smd: 2(0.737,0)
  Component Side region: 0.075,0.1 0.075,-0.1 0.425,-0.45 0.575,-0.45 0.575,0.45 0.425,0.45
  Component Side region: -0.452,0.1 -0.102,0.45 -0.552,0.45 -0.552,-0.45 -0.102,-0.45 -0.452,-0.1
  silkscreen extent -1.27,-0.64 1.27,0.64, body extent -0.8,-0.38 0.8,0.42, height 0.45
SOT23-6L [mm] "SOT23127P600-8N"
  rect 1.2x0.7 smd: 1(-1.15,0.95) 2(-1.15,0) 3(-1.15,-0.95) 4(1.15,-0.95) 5(1.15,0) 6(1.15,0.95)
  silkscreen extent -2.28,-1.55 0.5,1.55, body extent -0.87,-1.52 0.87,1.53, height 1.45
SOT23-STYLE9 [mm] "SOT23-STYLE9"
  rect 0.7x1 smd: 1(0,0.1) 2(1.92,0.1) 3(0.96,2.4)
  silkscreen extent -0.6,-0.6 2.54,3.11, body extent -0.49,-0.05 2.43,2.46, height 0.98
SOT95P280X110-6N [mm] "SOT23, 6-Leads, Body 2.90x2.80mm, Pitch 0.95mm, IPC Medium Density"
  rect 1x0.6 smd: 1(-1.375,0.95) 2(-1.375,0) 3(-1.375,-0.95) 4(1.375,-0.95) 5(1.375,0) 6(1.375,0.95)
  silkscreen extent -2.48,-1.55 0.5,1.55, body extent -0.88,-1.52 0.87,1.53, height 1.1
SOT95P300X115-3N [mm] "SOT23, 3-Leads, Body 3.10x3.00mm, Pitch 0.95mm, IPC Medium Density"
  rect 1.05x0.7 smd: 1(-1.425,0.95) 2(-1.425,-0.95) 3(1.425,0)
  silkscreen extent -1.55,-1.55 0.9,1.97, body extent -0.9,-1.55 0.9,1.55, height 1.15
SOT-723 [mm]
  rect 0.5x0.37 smd: 1(-0.4,0.4) 2(-0.4,-0.4)
  rect 0.5x0.47 smd: 3(0.4,0)
  silkscreen extent -1.01,0.76 -0.76,1.01, body extent -0.45,-0.65 0.45,0.65, height 0.55
SRF2012-900YA [mm] "SRF2012-900YA Chip Array, Flat, 4-Leads, Pitch 0.74mm,  Body 1.20x2.00mm,  IPC Medium Density"
  rect 0.75x0.45 smd: 1(-1,0.37) 2(-1,-0.37) 3(1,-0.37) 4(1,0.37)
  silkscreen extent -1.83,-1.02 1.65,1.02, body extent -1.1,-0.7 1.1,0.7, height 1.4
"Test_Point 1mm" [mm]
  round 1 smd paste-0.5 mask+0: 1(0,0)
"TSSOP-20 6.5x6.4mm" [mil] "TSSOP-20pin"
  rect 70x16 smd: 1(0.1,-0.19)
  oval 70x16 smd: 2(0.1,-25.79) 3(0.1,-51.39) 4(0.1,-76.99) 5(0.1,-102.59) 6(0.1,-128.19) 7(0.1,-153.79) 8(0.1,-179.39) 9(0.1,-204.99) 10(0.1,-230.59) 11(238.1,-230.59) 12(238.1,-204.99) 13(238.1,-179.39) 14(238.1,-153.79) 15(238.1,-128.19) 16(238.1,-102.59) 17(238.1,-76.99) 18(238.1,-51.39) 19(238.1,-25.79) 20(238.1,-0.19)
  silkscreen extent 54,-245 184,15, body extent -18,-249 256,18, height 39
"UFL TO SMA" [mm]
  rect 2.5x2.5 hole 1.651: 1(0,5.08) 1(0,0) 1(5.08,5.08) 1(5.08,0)
  silkscreen extent -1.7,-1.71 6.81,6.73, body extent -1.02,-10.03 5.97,22.61, height 9.44

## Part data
C1 C3: "Capacitor. 100uF, 10V, 20%, X5R, 1210", Capacitance=100uF, Capacitor_Type=Ceramic, Manufacturer1="Taiyo Yuden", Manufacturer_Part_Number1=LMK325BJ107MM-T, Operating_Temperature="-55C ~ +85C", Package_Case="1210 (3225 Metric)", Temperature_Coefficient=X5R, Tolerance="+/- 20%", Voltage_Rating=10V
C2 C4 C5 C13 C14 C16 C17 C18 C19 C20 C21 C22 C23 C24 C25 C26 C28 C29 C30 C32 C33 C40 C41 C42 C43 C46 C47: library part 1000742, "Capacitor, 0.1 uF, 16V, 10%, X7R, 0402", Capacitance=0.10µF, Capacitor_Type=Ceramic, Manufacturer1=Kemet, Manufacturer2="Samsung Electro-Mechanics America, Inc", Manufacturer_Part_Number1=C0402C104K4RALTU, Manufacturer_Part_Number2=CL05B104KO5NNNC, Operating_Temperature="-55°C ~ 125°C", Package_Case="0402 (1005 Metric)", Temperature_Coefficient=X7R, Tolerance=±10%, Voltage_Rating=16V
C6: library part 1000737, "Capacitor, 10 uF, 10V, 20%, X5R, 0402", Capacitance=10µF, Capacitor_Type=Ceramic, Manufacturer1="Venkel LTD.", Manufacturer2="Samsung Electro-Mechanics America, Inc", Manufacturer_Part_Number1=C0402X5R100-106MNP, Manufacturer_Part_Number2=CL05A106MP8NUB8, Operating_Temperature="-55°C ~ 85°C", Package_Case="0402 (1005 Metric)", Temperature_Coefficient=X5R, Tolerance=±20%, Voltage_Rating=10V
C7 C8: library part 1000780, "Capacitor, 10 uF, 25V, 10%, X5R, 0805", Capacitance=10µF, Capacitor_Type=Ceramic, Manufacturer1="Samsung Electro-Mechanics America, Inc", Manufacturer_Part_Number1=CL21A106KAYNNNE, Operating_Temperature="-55°C ~ 85°C", Package_Case="0805 (2012 Metric)", Temperature_Coefficient=X5R, Tolerance=±10%, Voltage_Rating=25V
C9 C44: "Capacitor, 22 uF, 25V, 20%, X5R, 0603", Capacitance=22µF, Capacitor_Type=Ceramic, Manufacturer1="TDK Corporation", Manufacturer_Part_Number1=C1608X5R1A226M080AC, Operating_Temperature="-55°C ~ 85°C", Package_Case="0603 (1608 Metric)", Temperature_Coefficient=X5R, Tolerance=±20%, Voltage_Rating=10V
C10 C11 C37 C45: library part 1000742, "Capacitor, 0.1 uF, 16V, 10%, X7R, 0402", Capacitance=0.10µF, Capacitor_Type=Ceramic, Manufacturer1="Samsung Electro-Mechanics America, Inc", Manufacturer_Part_Number1=CL05B104KO5NNNC, Operating_Temperature="-55°C ~ 125°C", Package_Case="0402 (1005 Metric)", Temperature_Coefficient=X7R, Tolerance=±10%, Voltage_Rating=16V
C12: library part 1001496, "Capacitor, 270 pF, 50V, 5%, C0G/NPO, 0402", Capacitance="270 pF", Capacitor_Type=Ceramic, Manufacturer1="Taiyo Yuden", Manufacturer_Part_Number1=UMK105CG271JV-F, Operating_Temperature="-55°C ~ 125°C", Package_Case=0402, Temperature_Coefficient="C0G, NP0", Tolerance=5%, Voltage_Rating=50V
C15 C27: library part 1001497, "Capacitor, 3.3 nF, 50V, 10%, X7R, 0402", Capacitance=3.3nF, Capacitor_Type=Ceramic, Manufacturer1=Murata, Manufacturer_Part_Number1=GRM155R71H332KA01D, Operating_Temperature="-55°C ~ 125°C", Package_Case=0402, Temperature_Coefficient=X7R, Tolerance=10%, Voltage_Rating=50V
C31 C34 C35 C39: library part 1000757, "Capacitor, 0.1 uF, 50V, 10%, X7R, 0603", Capacitance="0.1 uF", Capacitor_Type=Ceramic, Manufacturer1="TDK Corporation", Manufacturer2="AVX Corporation", Manufacturer_Part_Number1=CGA3E2X7R1H104K080AA, Manufacturer_Part_Number2=06035C104KAT2A, Operating_Temperature="-55 to 125C", Package_Case=0603, Tolerance=10%, Voltage_Rating=50V
C36 C38: library part 1000736, "Capacitor, 1 uF, 10V, 10%, X5R, 0402", Capacitance=1µF, Capacitor_Type=Ceramic, Manufacturer1="AVX Corporation", Manufacturer2=Kemet, Manufacturer_Part_Number1=0402ZD105KAT4A, Manufacturer_Part_Number2=C0402C105K8PACTU, Operating_Temperature="-55°C ~ 85°C", Package_Case="0402 (1005 Metric)", Temperature_Coefficient=X5R, Tolerance=±10%, Voltage_Rating=10V
D1 D3 D4 D9: library part 1000348, "Diode, LED, Green, 6mcd, 569nm, 0805", Color=Green, Manufacturer1="Lite-On Inc", Package_Case="0805 (2012 Metric)", Voltage_Forward_VF_Typical=-
D2 D6 D11 D12: library part 1000505, "Diode, Schottky, Dual, COM CATHODE, 30V, 0.35VF, 200MA, SOT23", Current_Average_Rectified_IO="200mA (DC)", Current_Reverse_Leakage_at_Vref="2µA @ 25V", Manufacturer1="ON Semiconductor", Package_Case="TO-236-3, SC-59, SOT-23-3", Voltage_DC_Reverse_VR_Max=30V, Voltage_Forward_VF_Max_at_I_Forward="800mV @ 100mA"
D5: library part 1000229, "Diode, Schottky, 40V, 0.500 Vf, 3A, SMA", Current_Average_Rectified_IO=3A, Current_Reverse_Leakage_at_Vref="500µA @ 40V", Manufacturer1="Diodes Incorporated", Operating_Temperature="-55°C ~ 150°C", Package_Case="DO-214AC, SMA", Voltage_DC_Reverse_VR_Max=40V, Voltage_Forward_VF_Max_at_I_Forward="500mV @ 3A"
D7: library part 1000349, "Diode, LED, BGO, 180mcd-450mcd-180mcd, 2.1x1.6mm", Color="Blue, Green, Orange (BGO)", Current_Test="20mA Blue, 20mA Green, 20mA Orange", Manufacturer1="Lite-On Inc", Manufacturer_Part_Number1=LTST-C19FD1WT, Millicandela_Rating="Blue: 180mcd, Green: 450mcd, Orange: 180mcd", Operating_Temperature="-20C to 80C", Package_Case="4-SMD, No Lead", Voltage_Forward_VF_Typical="3.5V Blue, 3.5V Green, 2V Orange"
D8: library part 1000185, "Diode, TVS, Unidirectional, 17V, 14.5A, SMA", Current_Peak_Pulse=14.5A, Manufacturer1="Bourns Inc", Operating_Temperature="-55°C ~ 150°C (TJ)", Package_Case="DO-214AC, SMA", Voltage_DC_Reverse_VR_Max=-
D10: library part 1001613, "Diode, TVS, USB, ESD, Unidirectional, 5.25V, 5A, 4CH, SOT23-6", Capacitance_at_Frequency=3pF@1MHz, Current_Peak_Pulse=5A, Current_Reverse_Leakage_at_Vref=10nA, Manufacturer1=STMicroelectronics, Operating_Temperature="-40 to +125C", Package_Case=SOT23-6, Voltage_DC_Reverse_VR_Max=5.25V
D13: library part 1000504, "Diode, Schottky, Dual, COM ANODE, 30V, 0.35 Vf, 200MA, SOT23", Current_Average_Rectified_IO="200mA (DC)", Current_Reverse_Leakage_at_Vref="2µA @ 25V", Manufacturer1="ON Semiconductor", Package_Case="TO-236-3, SC-59, SOT-23-3", Voltage_DC_Reverse_VR_Max=30V, Voltage_Forward_VF_Max_at_I_Forward="800mV @ 100mA"
D14 D15: library part 1001966, "Diode, TVS, Unidirectional, 5V, SOD-923", Capacitance_at_Frequency="32pF @ 1MHz", Current_Reverse_Leakage_at_Vref=2.5uA, Manufacturer1="Toshiba Semiconductor and Storage", Manufacturer_Part_Number1=DF2S6.2FS,L3M, Voltage_DC_Reverse_VR_Max=5
FB1 FB2 FB3: library part 1002238, "Ferrite Bead, 120 ohm @100MHz, 3A, 30mOHM-DC, 0603", Manufacturer1="Samsung Electro-Mechanics America, Inc", Manufacturer2="Murata Electronics North America", Manufacturer_Part_Number1=CIS10P121AC, Manufacturer_Part_Number2=BLM18KG121TN1D, Operating_Temperature="-55°C ~ 125°C", Package_Case=0603, Resistance_at_Frequency="120 ohm @ 100 MHz", Resistance_DC="30 mOhm"
Fiducial1 Fiducial2 Fiducial3 Fiducial4 Fiducial5 Fiducial6: library part Fiducial
J1 J20: library part 1001255, "Connector, Header, Male, 2.54mm, 2x1, TH", Manufacturer1="Sullins Connector Solutions"
J2: library part 1001099, "Connector, Header, Male, 2.54mm, 3x1, TH", Color=Black, Manufacturer1="Wurth Electronics Inc"
J3 J4 J10: library part 1000873, "Connector, Header, Male, 2.54mm, 10x1, TH 8.08mm", Color=Black, Manufacturer1="Sullins Connector Solutions"
J5 J14: library part 1000127, "Connector, USB, Mini B, Right Angle, SMD", Manufacturer1=Amphenol, Manufacturer_Part_Number1=10033526-N3212LF
J6 J7 J8 J9: library part 1001260, "Connector, Header, Male, 2.00mm, 4x1, Right Angle, SMD", Manufacturer1="JST Sales America Inc"
J11 J12: library part 1000872, "Connector, Header, Male, 2.54mm, 8x1, TH, 8.08mm", Color=Black, Manufacturer1="Sullins Connector Solutions"
J13: library part 1000871, "Connector, Header, Male, 2.54mm, 6x1, TH, 8.08mm", Color=Black, Manufacturer1="Sullins Connector Solutions"
J15: library part 1000221, "Connector, Barrel, 24V, 2.5A, 2.1mm ID, 5.5mm OD", Color=Black, Current_Rating=2.5A, Manufacturer1="CUI Inc", Manufacturer_Part_Number1=PJ-002A, Operating_Temperature="-25°C ~ 85°C", Voltage_Rating=24VDC
J16 J17: library part 1000732, "Connector, ANT, UFL to PCB Mount SMA, UFL Down, 53mm, TH", Manufacturer1="ROHO COMMUNICATION TECHNOLOGY CO. Ltd", Manufacturer_Part_Number1=RFSMARA-7053-DOWN
J18 J19: "Connector, Female, 2.00mm, 10x1, SMD, Left Oriented", Color=Black, Current_Rating=2A, Manufacturer1="Sullins Connector Solutions", Manufacturer_Part_Number1=NPPN101BFLC-RC, Operating_Temperature="-40°C ~ 105°C", Voltage_Rating=150V
L1: library part 1002239, "Inductor, 3.3 uH, 3.3A, 30%, 35.1 mOhm, Shielded, 4.90x4.90x2.00mm", Current_Rating=3.3A, Current_Saturation=4A, DC_Resistance="35.1 mOhm", Frequency_Self_Resonant=32MHz, Inductance=3.3uH, Inductor_Type=Wirewound, Manufacturer1="Taiyo Yuden", Manufacturer_Part_Number1=NRS5040T3R3NMGJV, Operating_Temperature="-40C to 125C", Tolerance=30%
L2: library part 1000187, "Common Mode Choke, 0.400A, 90Ohm, 300mOhm-DC, 2LN, SMD", Manufacturer1="Bourns Inc", Operating_Temperature="-40°C ~ 125°C", Package_Case="Horizontal, 4 PC Pad", Resistance_at_Frequency="90 Ohm @ 100MHz", Resistance_DC="300 mOhm Max"
Q1 Q2 Q3 Q4 Q5 Q6 Q7: library part 1001919, "Transistor, MOSFET, N-CH, 20V, 0.100A, SOT-723", Current_Continuous_Drain_at_25_deg_C=100mA, Drain_to_Source_Voltage=20V, Manufacturer1="Rohm Semiconductor", Manufacturer_Part_Number1=RUM001L02T2CL, Operating_Temperature="-55 to 150C", Package_Case=SOT-723, Power_Max="150 mW"
Q8: library part 1001920, "Transistor, MOSFET, P-CH, 20V, 4.2A, SOT-23-3", Current_Continuous_Drain_at_25_deg_C="4.2 A", Drain_to_Source_Voltage=20V, Manufacturer1="Diodes Incorporated", Manufacturer_Part_Number1=DMG2305UX-13, Manufacturer_Part_Number2=DMG2305UX-7, Operating_Temperature="-55 to 150C", Package_Case=SOT-23, Power_Max=1.4W
R1 R58 R59: library part 1001162, "Resistor, 330, 1%, 1/10W, 0402", Manufacturer1="Panasonic Electronic Components", Manufacturer_Part_Number1=ERJ-2RKF3300X, Operating_Temperature="-55°C ~ 155°C", Power="0.1W, 1/10W", Resistance_Ohms=330, Resistor_Package="0402 (1005 Metric)", Temperature_Coefficient=±100ppm/°C, Tolerance=±1%
R2 R60: library part 1000797, "Resistor, 1M, 1%, 1/16W, 0402", Manufacturer1="Samsung Electro-Mechanics America, Inc", Manufacturer_Part_Number1=RC1005F105CS, Operating_Temperature="-55°C ~ 155°C", Power="0.063W, 1/16W", Resistance_Ohms=1M, Resistor_Package="0402 (1005 Metric)", Temperature_Coefficient=±100ppm/°C, Tolerance=±1%
R3 R4: library part 1001176, "Resistor, 0.1, 1%, 1/4W, 0603", Manufacturer1="Panasonic Electronic Components", Manufacturer_Part_Number1=ERJ-L06KF10CV, Operating_Temperature="-55°C ~ 125°C", Power="0.25W, 1/4W", Resistance_Ohms=0.1, Resistor_Package="0805 (2012 Metric)", Temperature_Coefficient=±100ppm/°C, Tolerance=±1%
R5 R13 R27 R28 R29: library part 1000613, "Resistor, 2K, 1%, 1/10W, 0603", Manufacturer1="Panasonic Electronic Components", Manufacturer_Part_Number1=ERJ-3EKF2001V, Operating_Temperature="-55°C ~ 155°C", Power="0.1W, 1/10W", Resistance_Ohms=2k, Resistor_Package="0603 (1608 Metric)", Temperature_Coefficient=±100ppm/°C, Tolerance=±1%
R6 R7 R37: library part 1000794, "Resistor, 1K, 1%, 1/16W, 0402", Manufacturer1="Bourns Inc", Manufacturer2="Samsung Electro-Mechanics America, Inc", Manufacturer_Part_Number1=CR0402-FX-1001GLF, Manufacturer_Part_Number2=RC1005F102CS, Operating_Temperature="-55°C ~ 155°C", Power="0.063W, 1/16W", Resistance_Ohms=1k, Resistor_Package="0402 (1005 Metric)", Temperature_Coefficient=±100ppm/°C, Tolerance=±1%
